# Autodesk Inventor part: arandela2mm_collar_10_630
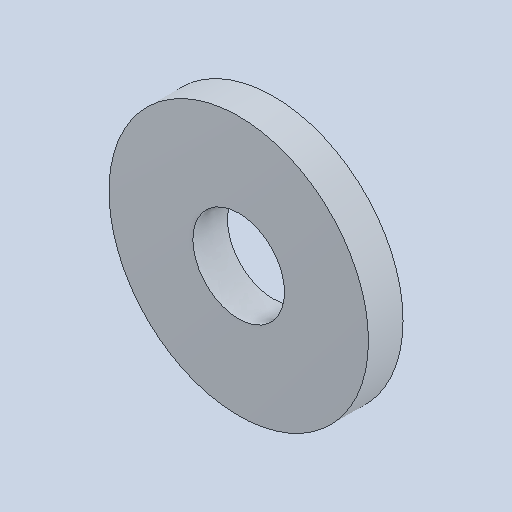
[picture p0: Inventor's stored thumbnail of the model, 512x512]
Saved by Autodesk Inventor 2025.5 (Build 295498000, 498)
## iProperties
Created: 2026-10
Part Number: arandela2mm_collar_10_630
Material: Genérico
Document SubType Name: Modeling
Designer: Luis M
Density: 1 g/cm^3
Appearance: Valor por defecto
Author: Luis M
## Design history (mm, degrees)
feature "Base1"
node "Sólido1"
